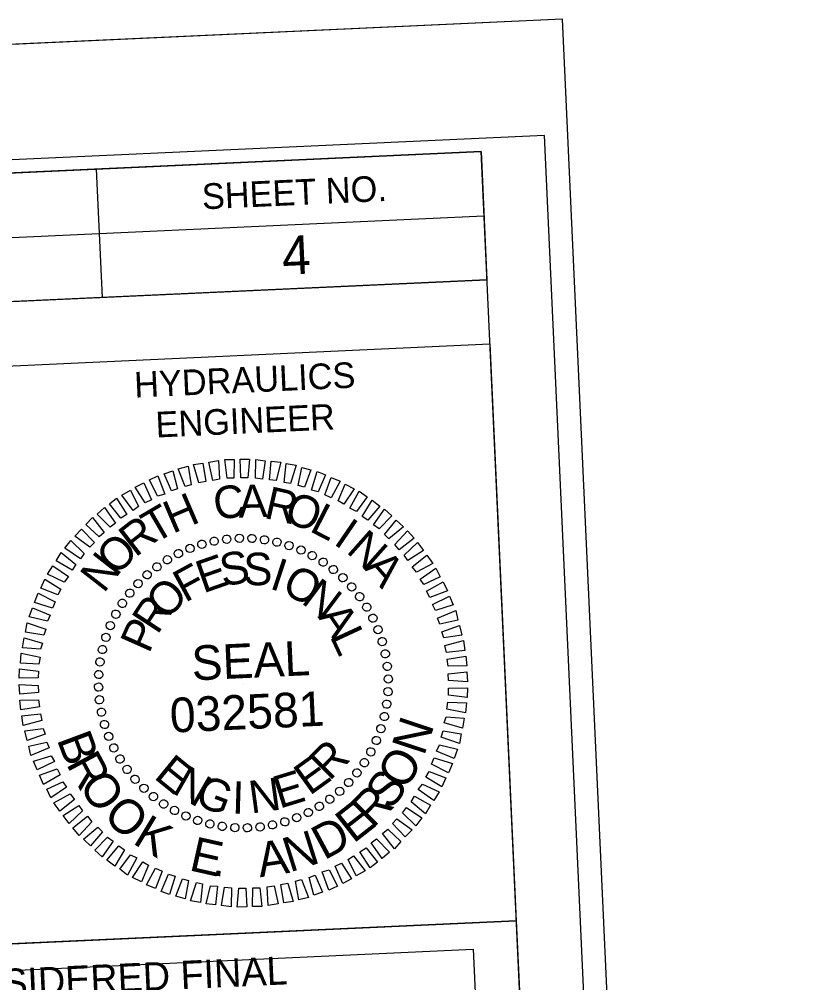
# Model space of a CAD drawing. Extents: x 1191067 to 1191874, y 892813 to 893283.
# Drawn here: x 1191747.5 to 1191807.9, y 893208.4 to 893283.5 of the extents above; entities that cross this region are included whole.
import ezdxf

# ---------------------------------------------------------------- set-up
doc = ezdxf.new("R2010")
doc.units = 0
for name, color, linetype in [('Sheet Border Standard 30in CELL', 7, 'Continuous'), ('Sheet Clip Boundary CELL', 7, 'Continuous'), ('Sheet Cutting Line CELL', 7, 'Continuous'), ('Sheet Data Field CELL', 7, 'Continuous'), ('Sheet PE Seal Cell', 7, 'Continuous'), ('Sheet Plot Border Inside CELL', 7, 'Continuous'), ('Sheet Plot Border Outside CELL', 7, 'Continuous'), ('Sheet Sticker Exception Certification CELL', 7, 'Continuous')]:
    doc.layers.add(name, color=color, linetype=linetype)

# ---------------------------------------------------------------- blocks, each defined once
blk = doc.blocks.new('STICKER EXCEPTION CERTIFICATION')
at = {"layer": 'Sheet Sticker Exception Certification CELL'}
for p, q in [((0, -0.47), (0, 0)), ((0, 0), (4.0008, 0)), ((4.0008, -0.0003), (4.0008, -0.4703)), ((4.0008, -0.47), (0, -0.47))]:
    blk.add_line(p, q, dxfattribs=at)
for s, p in [('DOCUMENT NOT CONSIDERED FINAL', (0.4214, -0.2069)), ('UNLESS ALL SIGNATURES COMPLETED', (0.32, -0.3829))]:
    blk.add_text(s, height=0.11, dxfattribs=at).set_placement(p)

msp = doc.modelspace()

# ---------------------------------------------------------------- linework, layer by layer
at = {"layer": 'Sheet Border Standard 30in CELL'}
for p, q in [((1191753.517, 893271.777), (1191753.974, 893261.787)), ((1191703.778, 893264.496), (1191783.714, 893268.153)), ((1191704.007, 893259.501), (1191783.943, 893263.158)), ((1191704.007, 893259.501), (1191783.943, 893263.158))]:
    msp.add_line(p, q, dxfattribs=at)
for points in [[(1191783.485, 893273.168), (1191184.112, 893245.747), (1191203.307, 892826.185), (1191802.68, 892853.607)], [(1191703.549, 893269.511), (1191783.485, 893273.168), (1191783.943, 893263.158), (1191704.007, 893259.501)], [(1191744.213, 893256.336), (1191784.171, 893258.164), (1191786.228, 893213.211), (1191746.27, 893211.383)]]:
    msp.add_lwpolyline(points, close=True, dxfattribs=at)
at = {"layer": 'Sheet Clip Boundary CELL'}
msp.add_lwpolyline([(1191202.887, 892905.773), (1191187.262, 893244.077), (1191701.27, 893267.817), (1191704.062, 893207.365), (1191782.861, 893211.004), (1191795.705, 892932.916), (1191477.617, 892917.949)], close=True, dxfattribs=at)
at = {"layer": 'Sheet Cutting Line CELL'}
msp.add_line((1191789.821, 893283.468), (1191116.925, 893252.683), dxfattribs=at)
at = {"layer": 'Sheet PE Seal Cell'}
for p, q in [((1191761.731, 893242.555), (1191761.731, 893242.555)), ((1191762.711, 893242.78), (1191762.711, 893242.78)), ((1191763.672, 893242.959), (1191763.672, 893242.959)), ((1191764.66, 893243.027), (1191764.66, 893243.027)), ((1191765.652, 893243.005), (1191765.652, 893243.005)), ((1191766.625, 893242.892), (1191766.625, 893242.892)), ((1191767.579, 893242.732), (1191767.579, 893242.732)), ((1191768.537, 893242.461), (1191768.537, 893242.461)), ((1191759.916, 893241.841), (1191759.916, 893241.841)), ((1191760.799, 893242.242), (1191760.799, 893242.242)), ((1191769.455, 893242.098), (1191769.455, 893242.098)), ((1191770.352, 893241.688), (1191770.352, 893241.688)), ((1191759.06, 893241.352), (1191759.06, 893241.352)), ((1191771.187, 893241.163), (1191771.187, 893241.163)), ((1191757.469, 893240.198), (1191757.469, 893240.198)), ((1191758.23, 893240.796), (1191758.23, 893240.796)), ((1191772.001, 893240.592), (1191772.001, 893240.592)), ((1191756.758, 893239.49), (1191756.758, 893239.49)), ((1191772.729, 893239.95), (1191772.729, 893239.95)), ((1191756.116, 893238.762), (1191756.116, 893238.762)), ((1191773.437, 893239.239), (1191773.437, 893239.239)), ((1191755.545, 893237.948), (1191755.545, 893237.948)), ((1191774.035, 893238.478), (1191774.035, 893238.478)), ((1191774.591, 893237.648), (1191774.591, 893237.648)), ((1191755.02, 893237.113), (1191755.02, 893237.113)), ((1191775.08, 893236.792), (1191775.08, 893236.792)), ((1191754.61, 893236.215), (1191754.61, 893236.215)), ((1191775.481, 893235.909), (1191775.481, 893235.909)), ((1191754.247, 893235.298), (1191754.247, 893235.298)), ((1191775.794, 893234.977), (1191775.794, 893234.977)), ((1191753.975, 893234.34), (1191753.975, 893234.34)), ((1191776.019, 893233.997), (1191776.019, 893233.997)), ((1191753.816, 893233.386), (1191753.816, 893233.386)), ((1191776.198, 893233.036), (1191776.198, 893233.036)), ((1191753.703, 893232.413), (1191753.703, 893232.413)), ((1191776.266, 893232.048), (1191776.266, 893232.048)), ((1191753.681, 893231.421), (1191753.681, 893231.421)), ((1191764.973, 893231.734), (1191764.973, 893231.734)), ((1191753.749, 893230.433), (1191753.749, 893230.433)), ((1191776.244, 893231.056), (1191776.244, 893231.056)), ((1191776.131, 893230.083), (1191776.131, 893230.083)), ((1191753.928, 893229.472), (1191753.928, 893229.472)), ((1191775.972, 893229.129), (1191775.972, 893229.129)), ((1191754.153, 893228.492), (1191754.153, 893228.492)), ((1191775.7, 893228.171), (1191775.7, 893228.171)), ((1191754.466, 893227.56), (1191754.466, 893227.56)), ((1191754.867, 893226.677), (1191754.867, 893226.677)), ((1191775.337, 893227.253), (1191775.337, 893227.253)), ((1191774.927, 893226.356), (1191774.927, 893226.356)), ((1191755.356, 893225.821), (1191755.356, 893225.821)), ((1191774.402, 893225.521), (1191774.402, 893225.521)), ((1191755.912, 893224.991), (1191755.912, 893224.991)), ((1191773.831, 893224.707), (1191773.831, 893224.707)), ((1191756.51, 893224.23), (1191756.51, 893224.23)), ((1191773.189, 893223.979), (1191773.189, 893223.979)), ((1191757.218, 893223.519), (1191757.218, 893223.519)), ((1191772.478, 893223.271), (1191772.478, 893223.271)), ((1191757.946, 893222.877), (1191757.946, 893222.877)), ((1191758.76, 893222.306), (1191758.76, 893222.306)), ((1191771.717, 893222.673), (1191771.717, 893222.673)), ((1191759.595, 893221.781), (1191759.595, 893221.781)), ((1191770.031, 893221.628), (1191770.031, 893221.628)), ((1191770.887, 893222.117), (1191770.887, 893222.117)), ((1191760.492, 893221.371), (1191760.492, 893221.371)), ((1191761.41, 893221.008), (1191761.41, 893221.008)), ((1191762.368, 893220.736), (1191762.368, 893220.736)), ((1191767.236, 893220.689), (1191767.236, 893220.689)), ((1191768.216, 893220.914), (1191768.216, 893220.914)), ((1191769.148, 893221.227), (1191769.148, 893221.227)), ((1191763.322, 893220.577), (1191763.322, 893220.577)), ((1191764.295, 893220.464), (1191764.295, 893220.464)), ((1191765.287, 893220.442), (1191765.287, 893220.442)), ((1191766.275, 893220.51), (1191766.275, 893220.51))]:
    msp.add_line(p, q, dxfattribs=at)
for points in [[(1191764.783, 893247.717), (1191764.716, 893249.178), (1191765.459, 893249.19), (1191765.323, 893247.72)], [(1191760.444, 893247.046), (1191759.907, 893248.44), (1191760.664, 893248.633), (1191760.911, 893247.18)], [(1191761.512, 893247.343), (1191761.086, 893248.765), (1191761.825, 893248.866), (1191762.048, 893247.435)], [(1191762.584, 893247.527), (1191762.271, 893248.954), (1191763.031, 893249.079), (1191763.121, 893247.619)], [(1191763.703, 893247.691), (1191763.524, 893249.146), (1191764.266, 893249.158), (1191764.243, 893247.693)], [(1191765.91, 893247.701), (1191765.933, 893249.166), (1191766.681, 893249.066), (1191766.453, 893247.636)], [(1191766.997, 893247.571), (1191767.133, 893249.019), (1191767.88, 893248.94), (1191767.539, 893247.528)], [(1191768.154, 893247.376), (1191768.312, 893248.847), (1191769.085, 893248.703), (1191768.632, 893247.285)], [(1191769.247, 893247.133), (1191769.52, 893248.542), (1191770.227, 893248.349), (1191769.726, 893246.998)], [(1191758.294, 893246.294), (1191757.65, 893247.571), (1191758.311, 893247.872), (1191758.849, 893246.455)], [(1191759.378, 893246.704), (1191758.8, 893248.029), (1191759.487, 893248.263), (1191759.843, 893246.883)], [(1191770.277, 893246.775), (1191770.729, 893248.215), (1191771.37, 893247.974), (1191770.801, 893246.641)], [(1191771.308, 893246.394), (1191771.809, 893247.746), (1191772.52, 893247.463), (1191771.813, 893246.17)], [(1191757.326, 893245.777), (1191756.549, 893247.003), (1191757.232, 893247.349), (1191757.811, 893246.002)], [(1191772.365, 893245.925), (1191772.913, 893247.234), (1191773.605, 893246.882), (1191772.805, 893245.674)], [(1191756.384, 893245.193), (1191755.497, 893246.369), (1191756.178, 893246.761), (1191756.799, 893245.483)], [(1191773.27, 893245.358), (1191773.997, 893246.697), (1191774.603, 893246.252), (1191773.776, 893245.111)], [(1191755.421, 893244.586), (1191754.537, 893245.695), (1191755.102, 893246.148), (1191755.903, 893244.879)], [(1191774.222, 893244.726), (1191774.997, 893246), (1191775.604, 893245.532), (1191774.663, 893244.431)], [(1191754.598, 893243.873), (1191753.582, 893244.908), (1191754.167, 893245.407), (1191755.012, 893244.185)], [(1191775.108, 893244.068), (1191775.976, 893245.279), (1191776.54, 893244.764), (1191775.55, 893243.75)], [(1191753.731, 893243.135), (1191752.696, 893244.079), (1191753.211, 893244.643), (1191754.143, 893243.469)], [(1191775.953, 893243.318), (1191776.871, 893244.419), (1191777.435, 893243.904), (1191776.307, 893242.974)], [(1191753.025, 893242.314), (1191751.836, 893243.184), (1191752.375, 893243.726), (1191753.368, 893242.69)], [(1191776.777, 893242.545), (1191777.764, 893243.604), (1191778.264, 893243.019), (1191777.112, 893242.11)], [(1191752.277, 893241.424), (1191751.068, 893242.247), (1191751.536, 893242.854), (1191752.574, 893241.843)], [(1191777.491, 893241.699), (1191778.549, 893242.694), (1191779.006, 893242.062), (1191777.78, 893241.285)], [(1191751.642, 893240.539), (1191750.393, 893241.248), (1191750.791, 893241.919), (1191751.915, 893240.98)], [(1191778.118, 893240.805), (1191779.27, 893241.713), (1191779.728, 893241.058), (1191778.453, 893240.37)], [(1191751.009, 893239.609), (1191749.719, 893240.226), (1191750.14, 893240.876), (1191751.35, 893240.03)], [(1191778.747, 893239.842), (1191779.97, 893240.687), (1191780.294, 893240.003), (1191779.037, 893239.428)], [(1191750.514, 893238.618), (1191749.207, 893239.122), (1191749.512, 893239.834), (1191750.764, 893239.058)], [(1191779.241, 893238.896), (1191780.536, 893239.631), (1191780.861, 893238.926), (1191779.488, 893238.412)], [(1191750.112, 893237.564), (1191748.694, 893238.017), (1191749, 893238.729), (1191750.314, 893238.069)], [(1191779.694, 893237.859), (1191781.038, 893238.506), (1191781.317, 893237.82), (1191779.94, 893237.397)], [(1191749.707, 893236.554), (1191748.295, 893236.895), (1191748.555, 893237.605), (1191749.933, 893237.038)], [(1191780.103, 893236.796), (1191781.518, 893237.379), (1191781.687, 893236.643), (1191780.282, 893236.331)], [(1191749.419, 893235.46), (1191748.013, 893235.688), (1191748.136, 893236.437), (1191749.578, 893235.94)], [(1191780.422, 893235.73), (1191781.818, 893236.221), (1191781.988, 893235.463), (1191780.578, 893235.264)], [(1191749.177, 893234.368), (1191747.775, 893234.484), (1191747.897, 893235.255), (1191749.335, 893234.848)], [(1191780.674, 893234.66), (1191782.12, 893235.042), (1191782.223, 893234.28), (1191780.788, 893234.125)], [(1191749.049, 893233.213), (1191747.605, 893233.282), (1191747.66, 893234.051), (1191749.137, 893233.758)], [(1191780.858, 893233.587), (1191782.311, 893233.834), (1191782.391, 893233.072), (1191780.928, 893233.05)], [(1191748.986, 893232.129), (1191747.523, 893232.107), (1191747.534, 893232.851), (1191749.006, 893232.671)], [(1191780.932, 893232.465), (1191782.39, 893232.599), (1191782.425, 893231.835), (1191780.956, 893231.925)], [(1191749.015, 893231.004), (1191747.557, 893230.87), (1191747.522, 893231.634), (1191748.99, 893231.544)], [(1191780.961, 893231.34), (1191782.424, 893231.362), (1191782.413, 893230.618), (1191780.94, 893230.798)], [(1191749.089, 893229.882), (1191747.636, 893229.635), (1191747.556, 893230.397), (1191749.019, 893230.419)], [(1191780.898, 893230.256), (1191782.342, 893230.187), (1191782.287, 893229.418), (1191780.81, 893229.711)], [(1191749.273, 893228.809), (1191747.827, 893228.427), (1191747.724, 893229.188), (1191749.159, 893229.344)], [(1191780.77, 893229.101), (1191782.172, 893228.985), (1191782.05, 893228.214), (1191780.612, 893228.621)], [(1191749.525, 893227.739), (1191748.128, 893227.247), (1191747.959, 893228.005), (1191749.368, 893228.205)], [(1191780.527, 893228.009), (1191781.934, 893227.78), (1191781.811, 893227.032), (1191780.369, 893227.529)], [(1191749.844, 893226.673), (1191748.429, 893226.09), (1191748.26, 893226.825), (1191749.665, 893227.138)], [(1191780.24, 893226.915), (1191781.652, 893226.574), (1191781.391, 893225.864), (1191780.014, 893226.431)], [(1191750.253, 893225.61), (1191748.909, 893224.963), (1191748.63, 893225.649), (1191750.007, 893226.072)], [(1191779.835, 893225.905), (1191781.253, 893225.452), (1191780.947, 893224.74), (1191779.633, 893225.4)], [(1191750.706, 893224.572), (1191749.411, 893223.837), (1191749.086, 893224.543), (1191750.458, 893225.057)], [(1191779.433, 893224.851), (1191780.74, 893224.347), (1191780.435, 893223.635), (1191779.183, 893224.411)], [(1191751.2, 893223.626), (1191749.977, 893222.782), (1191749.653, 893223.466), (1191750.91, 893224.041)], [(1191778.938, 893223.859), (1191780.227, 893223.243), (1191779.807, 893222.593), (1191778.597, 893223.438)], [(1191751.829, 893222.664), (1191750.677, 893221.756), (1191750.219, 893222.41), (1191751.494, 893223.099)], [(1191778.305, 893222.93), (1191779.553, 893222.221), (1191779.156, 893221.549), (1191778.032, 893222.489)], [(1191752.456, 893221.769), (1191751.398, 893220.775), (1191750.941, 893221.407), (1191752.167, 893222.184)], [(1191777.67, 893222.045), (1191778.878, 893221.221), (1191778.411, 893220.614), (1191777.373, 893221.626)], [(1191753.17, 893220.924), (1191752.183, 893219.865), (1191751.683, 893220.45), (1191752.835, 893221.359)], [(1191776.922, 893221.154), (1191778.11, 893220.285), (1191777.572, 893219.743), (1191776.579, 893220.778)], [(1191753.994, 893220.151), (1191753.076, 893219.05), (1191752.512, 893219.565), (1191753.64, 893220.495)], [(1191776.216, 893220.334), (1191777.25, 893219.39), (1191776.736, 893218.826), (1191775.804, 893220)], [(1191754.839, 893219.401), (1191753.971, 893218.19), (1191753.407, 893218.705), (1191754.397, 893219.718)], [(1191775.349, 893219.596), (1191776.365, 893218.561), (1191775.78, 893218.062), (1191774.935, 893219.284)], [(1191755.725, 893218.743), (1191754.95, 893217.469), (1191754.343, 893217.937), (1191755.284, 893219.038)], [(1191774.526, 893218.883), (1191775.41, 893217.774), (1191774.845, 893217.321), (1191774.044, 893218.59)], [(1191756.677, 893218.111), (1191755.95, 893216.771), (1191755.344, 893217.217), (1191756.171, 893218.358)], [(1191757.582, 893217.544), (1191757.034, 893216.235), (1191756.342, 893216.587), (1191757.142, 893217.794)], [(1191772.621, 893217.692), (1191773.398, 893216.466), (1191772.715, 893216.119), (1191772.136, 893217.467)], [(1191773.563, 893218.275), (1191774.45, 893217.1), (1191773.769, 893216.708), (1191773.148, 893217.986)], [(1191758.639, 893217.075), (1191758.138, 893215.723), (1191757.427, 893216.006), (1191758.134, 893217.299)], [(1191771.653, 893217.175), (1191772.297, 893215.898), (1191771.635, 893215.597), (1191771.098, 893217.014)], [(1191759.67, 893216.694), (1191759.218, 893215.254), (1191758.576, 893215.495), (1191759.146, 893216.828)], [(1191760.7, 893216.336), (1191760.427, 893214.927), (1191759.72, 893215.119), (1191760.221, 893216.471)], [(1191761.793, 893216.093), (1191761.635, 893214.621), (1191760.862, 893214.766), (1191761.315, 893216.184)], [(1191769.503, 893216.423), (1191770.04, 893215.029), (1191769.283, 893214.836), (1191769.036, 893216.289)], [(1191770.568, 893216.764), (1191771.147, 893215.44), (1191770.46, 893215.205), (1191770.104, 893216.586)], [(1191762.95, 893215.898), (1191762.814, 893214.45), (1191762.067, 893214.529), (1191762.408, 893215.941)], [(1191764.037, 893215.767), (1191764.014, 893214.302), (1191763.266, 893214.403), (1191763.494, 893215.833)], [(1191765.164, 893215.751), (1191765.231, 893214.29), (1191764.488, 893214.279), (1191764.624, 893215.749)], [(1191766.244, 893215.778), (1191766.423, 893214.323), (1191765.68, 893214.311), (1191765.704, 893215.776)], [(1191767.363, 893215.942), (1191767.676, 893214.515), (1191766.916, 893214.39), (1191766.826, 893215.85)], [(1191768.435, 893216.126), (1191768.861, 893214.704), (1191768.122, 893214.603), (1191767.899, 893216.034)]]:
    msp.add_lwpolyline(points, close=True, dxfattribs=at)
for centre, major_axis in [((1191763.672, 893242.945), (-0.037, 0.322)), ((1191764.655, 893243.016), (-0.009, 0.324)), ((1191765.639, 893243.001), (0.019, 0.323)), ((1191766.618, 893242.9), (0.047, 0.321)), ((1191760.815, 893242.226), (-0.119, 0.301)), ((1191761.746, 893242.549), (-0.093, 0.31)), ((1191762.7, 893242.789), (-0.065, 0.317)), ((1191767.585, 893242.714), (0.075, 0.315)), ((1191768.532, 893242.445), (0.102, 0.307)), ((1191769.452, 893242.094), (0.129, 0.297)), ((1191759.056, 893241.345), (-0.17, 0.276)), ((1191759.917, 893241.824), (-0.145, 0.29)), ((1191770.338, 893241.664), (0.154, 0.285)), ((1191758.241, 893240.793), (-0.193, 0.26)), ((1191771.183, 893241.159), (0.178, 0.271)), ((1191771.981, 893240.582), (0.201, 0.254)), ((1191757.478, 893240.172), (-0.215, 0.242)), ((1191772.725, 893239.937), (0.223, 0.235)), ((1191756.771, 893239.486), (-0.235, 0.223)), ((1191773.411, 893239.23), (0.242, 0.215)), ((1191756.126, 893238.742), (-0.254, 0.201)), ((1191774.032, 893238.467), (0.26, 0.193)), ((1191755.549, 893237.944), (-0.271, 0.178)), ((1191774.584, 893237.651), (0.276, 0.17)), ((1191755.044, 893237.099), (-0.285, 0.154)), ((1191754.614, 893236.213), (-0.297, 0.129)), ((1191775.063, 893236.791), (0.29, 0.145)), ((1191775.466, 893235.893), (0.301, 0.119)), ((1191754.263, 893235.293), (-0.307, 0.102)), ((1191775.788, 893234.962), (0.31, 0.093)), ((1191753.994, 893234.346), (-0.315, 0.075)), ((1191776.028, 893234.008), (0.317, 0.065)), ((1191753.808, 893233.379), (-0.321, 0.047)), ((1191753.707, 893232.4), (-0.323, 0.019)), ((1191776.184, 893233.035), (0.322, 0.037)), ((1191776.255, 893232.053), (0.324, 0.009)), ((1191753.692, 893231.415), (-0.324, -0.009)), ((1191776.24, 893231.069), (0.323, -0.019)), ((1191753.763, 893230.433), (-0.322, -0.037)), ((1191776.139, 893230.09), (0.321, -0.047)), ((1191753.919, 893229.461), (-0.317, -0.065)), ((1191775.953, 893229.123), (0.315, -0.075)), ((1191754.159, 893228.506), (-0.31, -0.093)), ((1191775.684, 893228.176), (0.307, -0.102)), ((1191754.481, 893227.576), (-0.301, -0.119)), ((1191775.333, 893227.256), (0.297, -0.129)), ((1191754.884, 893226.678), (-0.29, -0.145)), ((1191774.903, 893226.37), (0.285, -0.154)), ((1191755.363, 893225.817), (-0.276, -0.17)), ((1191755.915, 893225.002), (-0.26, -0.193)), ((1191774.398, 893225.525), (0.271, -0.178)), ((1191756.536, 893224.238), (-0.242, -0.215)), ((1191773.821, 893224.727), (0.254, -0.201)), ((1191757.222, 893223.532), (-0.223, -0.235)), ((1191772.469, 893223.297), (0.215, -0.242)), ((1191773.176, 893223.983), (0.235, -0.223)), ((1191757.966, 893222.887), (-0.201, -0.254)), ((1191771.706, 893222.676), (0.193, -0.26)), ((1191758.764, 893222.31), (-0.178, -0.271)), ((1191759.609, 893221.805), (-0.154, -0.285)), ((1191770.89, 893222.124), (0.17, -0.276)), ((1191760.495, 893221.375), (-0.129, -0.297)), ((1191769.132, 893221.242), (0.119, -0.301)), ((1191770.03, 893221.645), (0.145, -0.29)), ((1191761.415, 893221.024), (-0.102, -0.307)), ((1191762.362, 893220.755), (-0.075, -0.315)), ((1191763.329, 893220.569), (-0.047, -0.321)), ((1191764.308, 893220.468), (-0.019, -0.323)), ((1191765.292, 893220.453), (0.009, -0.324)), ((1191766.274, 893220.524), (0.037, -0.322)), ((1191767.247, 893220.68), (0.065, -0.317)), ((1191768.201, 893220.92), (0.093, -0.31))]:
    msp.add_ellipse(centre, major_axis=major_axis, ratio=0.999708, dxfattribs=at)
at = {"layer": 'Sheet Plot Border Inside CELL'}
msp.add_lwpolyline([(1191788.433, 893274.415), (1191122.53, 893243.95), (1191141.818, 892822.351), (1191807.721, 892852.816)], close=True, dxfattribs=at)
at = {"layer": 'Sheet Plot Border Outside CELL'}
msp.add_lwpolyline([(1191789.821, 893283.468), (1191116.925, 893252.683), (1191137.034, 892813.143), (1191809.93, 892843.928)], close=True, dxfattribs=at)

# ---------------------------------------------------------------- block references
at = {"layer": 'Sheet Sticker Exception Certification CELL', "xscale": 20, "yscale": 19.999999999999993, "rotation": 2.619466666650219}
msp.add_blockref('STICKER EXCEPTION CERTIFICATION', (1191706.292, 893209.554), dxfattribs=at)

# ---------------------------------------------------------------- texts
at = {"layer": 'Sheet Border Standard 30in CELL'}
for s, p in [('SHEET NO.', (1191761.789, 893268.652)), ('HYDRAULICS', (1191756.514, 893253.975)), ('ENGINEER', (1191758.178, 893250.868))]:
    msp.add_text(s, height=2, rotation=2.61947, dxfattribs=at).set_placement(p)
at = {"layer": 'Sheet Data Field CELL'}
msp.add_text('4', height=3, rotation=2.61947, dxfattribs=at).set_placement((1191768.045, 893263.552))
at = {"layer": 'Sheet PE Seal Cell'}
for s, height, rotation, p in [('C', 2.537, 8.83934, (1191762.84, 893244.408)), ('A', 2.537, 1.63979, (1191764.609, 893244.624)), ('R', 2.537, 347.24056, (1191766.501, 893244.62)), ('H', 2.537, 23.23894, (1191759.464, 893243.352)), ('O', 2.537, 340.04063, (1191768.022, 893244.352)), ('T', 2.537, 30.43924, (1191758.037, 893242.544)), ('L', 2.537, 332.84034, (1191770.038, 893243.611)), ('R', 2.537, 37.63997, (1191756.554, 893241.485)), ('I', 2.537, 325.63961, (1191771.908, 893242.615)), ('O', 2.537, 44.84121, (1191755.067, 893240.02)), ('N', 2.537, 318.43837, (1191772.907, 893241.963)), ('N', 2.537, 52.04297, (1191754.093, 893238.669)), ('E', 2.537, 19.23053, (1191761.839, 893238.708)), ('S', 2.537, 9.87507, (1191763.368, 893239.251)), ('S', 2.537, 0.51987, (1191764.986, 893239.348)), ('F', 2.537, 28.5865, (1191760.431, 893237.968)), ('I', 2.537, 341.80907, (1191766.933, 893239.122)), ('A', 2.537, 311.23662, (1191774.294, 893240.697)), ('O', 2.537, 332.45295, (1191767.846, 893238.848)), ('O', 2.537, 47.30071, (1191759.009, 893236.574)), ('N', 2.537, 323.09608, (1191769.393, 893238.018)), ('R', 2.538, 56.65912, (1191758.272, 893235.437)), ('A', 2.538, 304.37973, (1191770.728, 893236.908)), ('P', 2.538, 66.01836, (1191757.619, 893233.966)), ('L', 2.538, 295.02032, (1191771.676, 893235.397)), ('SEAL', 2.6992, 2.61947, (1191761.001, 893231.935)), ('032581', 2.6992, 2.61947, (1191759.307, 893227.868)), ('N', 2.699, 71.62642, (1191779.045, 893225.988)), ('B', 2.699, 290.58332, (1191750.418, 893227.356)), ('R', 2.537, 45.10087, (1191771.677, 893224.045)), ('R', 2.699, 298.27995, (1191751.136, 893225.446)), ('E', 2.537, 320.89636, (1191757.923, 893224.362)), ('E', 2.537, 35.74356, (1191770.129, 893222.916)), ('O', 2.699, 60.06601, (1191777.607, 893223.284)), ('N', 2.537, 330.25342, (1191759.327, 893223.21)), ('O', 2.699, 305.76021, (1191752.072, 893223.699)), ('G', 2.537, 339.60971, (1191761.082, 893222.277)), ('E', 2.537, 17.03123, (1191767.787, 893221.93)), ('S', 2.699, 52.7403, (1191776.427, 893221.742)), ('I', 2.537, 358.32067, (1191764.065, 893221.557)), ('N', 2.537, 7.67586, (1191765.574, 893221.559)), ('R', 2.699, 45.26004, (1191775.028, 893220.336)), ('O', 2.699, 317.32062, (1191753.944, 893221.276)), ('E', 2.699, 38.1507, (1191773.541, 893219.179)), ('K', 2.699, 328.88102, (1191756.264, 893219.278)), ('D', 2.699, 28.27491, (1191771.26, 893217.896)), ('N', 2.699, 17.54908, (1191768.575, 893216.968)), ('E', 2.699, 347.3653, (1191760.662, 893217.159)), ('A', 2.699, 8.70877, (1191766.263, 893216.59)), ('.', 2.699, 354.47464, (1191762.499, 893216.738))]:
    msp.add_text(s, height=height, rotation=rotation, dxfattribs=at).set_placement(p)

doc.saveas('drawing.dxf')
